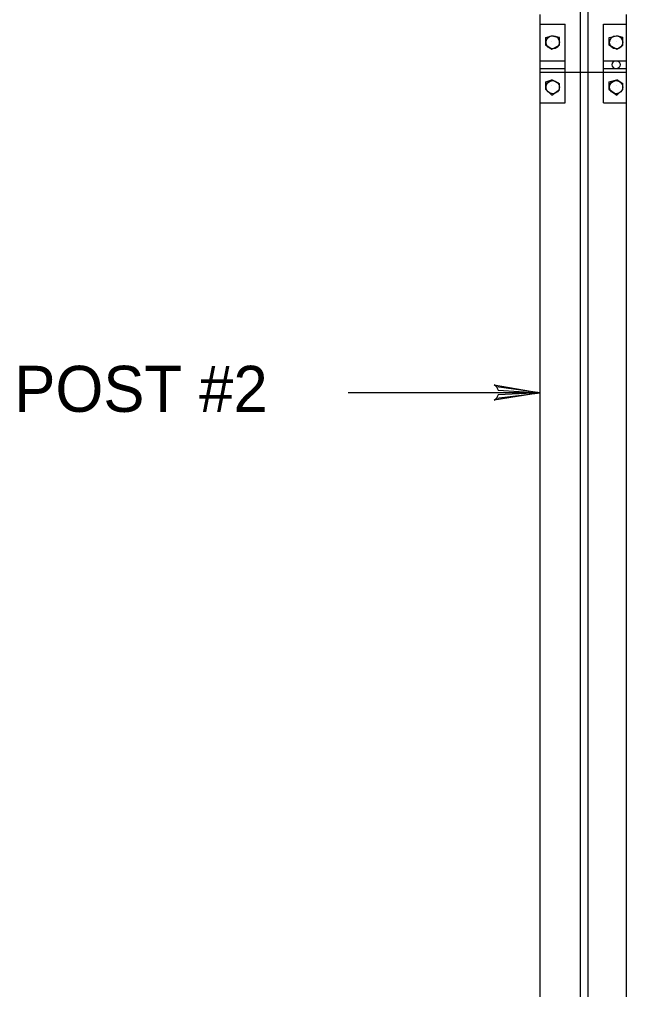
# Model space of a CAD drawing. Extents: x 637580 to 641008, y 294594 to 295782.
# Drawn here: x 637999.5 to 638039.1, y 295486.4 to 295549.6 of the extents above; entities that cross this region are included whole.
import ezdxf

# ---------------------------------------------------------------- set-up
doc = ezdxf.new("R2010")
doc.units = 0
doc.layers.add('2', color=7, linetype='Continuous')
doc.layers.add('3', color=7, linetype='Continuous')

# ---------------------------------------------------------------- blocks, each defined once
blk = doc.blocks.new('RARROW')
at = {"layer": '3'}
blk.add_lwpolyline([(-2.2695, 0.285), (-2.184875, 0.12075), (0, 0), (-2.2695, 0.285), (-2.38575, 0.384625), (0, 0), (-2.183125, -0.108), (-2.262875, -0.2705), (0, 0), (-2.38575, -0.379125), (-2.262875, -0.2705)], dxfattribs=at)

msp = doc.modelspace()

# ---------------------------------------------------------------- linework, layer by layer
at = {"layer": '2'}
for p, q in [((638036.062, 295453.501), (638036.062, 295676.876)), ((638036.562, 295453.501), (638036.562, 295676.876)), ((638033.437, 295461.126), (638033.437, 295549.876)), ((638039.062, 295461.126), (638039.062, 295549.876)), ((638033.437, 295549.251), (638035.062, 295549.251)), ((638035.062, 295544.126), (638035.062, 295549.251)), ((638037.562, 295549.251), (638039.062, 295549.251)), ((638037.562, 295544.126), (638037.562, 295549.251)), ((638033.812, 295548.376), (638034.187, 295548.501)), ((638033.812, 295548.376), (638034.187, 295548.501)), ((638034.187, 295548.501), (638034.687, 295548.376)), ((638034.687, 295548.376), (638034.187, 295548.501)), ((638037.937, 295548.376), (638038.437, 295548.501)), ((638037.937, 295548.376), (638038.437, 295548.501)), ((638038.437, 295548.501), (638038.812, 295548.376)), ((638038.812, 295548.376), (638038.437, 295548.501)), ((638033.812, 295547.876), (638033.812, 295548.376)), ((638033.812, 295547.876), (638033.812, 295548.376)), ((638033.812, 295547.876), (638034.187, 295547.626)), ((638034.187, 295547.626), (638033.812, 295547.876)), ((638034.187, 295548.126), (638034.187, 295548.126)), ((638034.187, 295547.626), (638034.687, 295547.876)), ((638034.187, 295547.626), (638034.687, 295547.876)), ((638034.687, 295547.876), (638034.687, 295548.376)), ((638034.687, 295547.876), (638034.687, 295548.376)), ((638037.937, 295547.876), (638037.937, 295548.376)), ((638037.937, 295547.876), (638037.937, 295548.376)), ((638037.937, 295547.876), (638038.437, 295547.626)), ((638038.437, 295547.626), (638037.937, 295547.876)), ((638038.437, 295548.126), (638038.437, 295548.126)), ((638038.437, 295547.626), (638038.812, 295547.876)), ((638038.437, 295547.626), (638038.812, 295547.876)), ((638038.812, 295547.876), (638038.812, 295548.376)), ((638038.812, 295547.876), (638038.812, 295548.376)), ((638033.437, 295546.876), (638035.062, 295546.876)), ((638037.562, 295546.876), (638039.062, 295546.876)), ((638038.437, 295546.751), (638038.437, 295546.751)), ((638033.437, 295546.376), (638035.062, 295546.376)), ((638033.437, 295546.126), (638033.437, 295546.126)), ((638033.437, 295546.126), (638035.062, 295546.126)), ((638033.437, 295546.126), (638033.437, 295546.126)), ((638035.062, 295546.126), (638037.562, 295546.126)), ((638037.562, 295546.376), (638039.062, 295546.376)), ((638037.562, 295546.126), (638039.062, 295546.126)), ((638033.812, 295545.501), (638034.187, 295545.626)), ((638033.812, 295545.376), (638034.187, 295545.626)), ((638033.812, 295545.001), (638033.812, 295545.501)), ((638033.812, 295545.001), (638033.812, 295545.376)), ((638034.187, 295545.626), (638034.687, 295545.376)), ((638034.687, 295545.376), (638034.187, 295545.626)), ((638034.187, 295545.251), (638034.187, 295545.251)), ((638034.687, 295545.001), (638034.687, 295545.376)), ((638034.687, 295545.001), (638034.687, 295545.376)), ((638037.937, 295545.501), (638038.437, 295545.626)), ((638037.937, 295545.376), (638038.437, 295545.626)), ((638037.937, 295545.001), (638037.937, 295545.501)), ((638037.937, 295545.001), (638037.937, 295545.376)), ((638038.437, 295545.626), (638038.812, 295545.376)), ((638038.812, 295545.376), (638038.437, 295545.626)), ((638038.437, 295545.251), (638038.437, 295545.251)), ((638038.812, 295545.001), (638038.812, 295545.376)), ((638038.812, 295545.001), (638038.812, 295545.376)), ((638033.812, 295545.001), (638034.187, 295544.626)), ((638034.187, 295544.626), (638033.812, 295545.001)), ((638034.187, 295544.626), (638034.687, 295545.001)), ((638034.187, 295544.626), (638034.687, 295545.001)), ((638037.937, 295545.001), (638038.437, 295544.626)), ((638038.437, 295544.626), (638037.937, 295545.001)), ((638038.437, 295544.626), (638038.812, 295545.001)), ((638038.437, 295544.626), (638038.812, 295545.001)), ((638033.437, 295544.126), (638035.062, 295544.126)), ((638037.562, 295544.126), (638039.062, 295544.126)), ((638033.437, 295525.251), (638020.937, 295525.251))]:
    msp.add_line(p, q, dxfattribs=at)
for centre, major_axis in [((638034.251, 295548.071), (0, -0.432)), ((638038.387, 295548.071), (0, -0.432)), ((638038.387, 295546.611), (0, 0.265)), ((638034.251, 295545.153), (0, -0.432)), ((638038.387, 295545.153), (0, -0.432))]:
    msp.add_ellipse(centre, major_axis=major_axis, ratio=0.996388, dxfattribs=at)

# ---------------------------------------------------------------- block references
at = {"layer": '2', "xscale": 1.2574347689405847, "yscale": 1.3092961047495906}
msp.add_blockref('RARROW', (638033.437, 295525.251), dxfattribs=at)

# ---------------------------------------------------------------- texts
at = {"layer": '3'}
msp.add_text('POST #2', height=3, dxfattribs=at).set_placement((637999.187, 295524.001))

doc.saveas('drawing.dxf')
